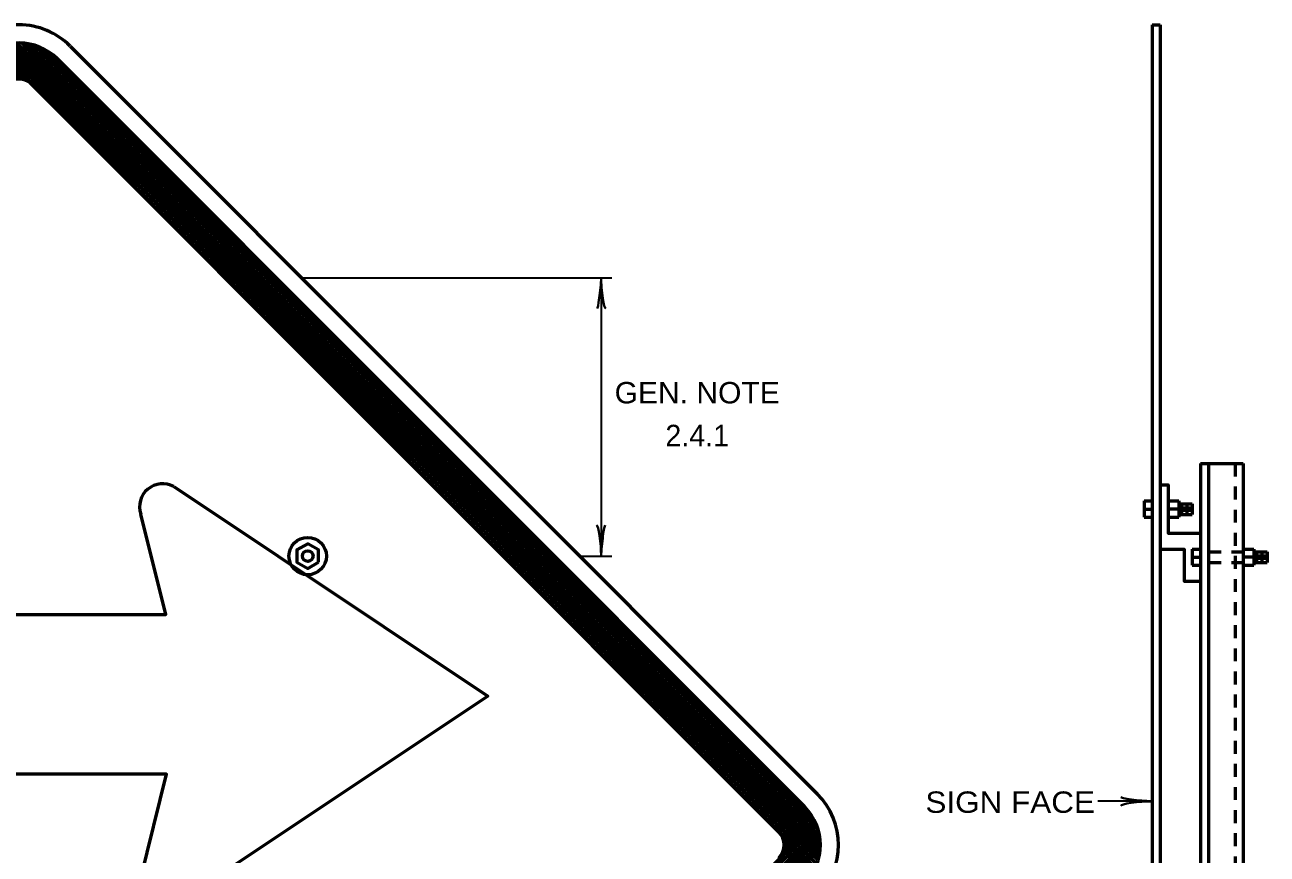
# Model space of a CAD drawing. Extents: x -87 to 768, y -466 to 78.
# Drawn here: x 318.2 to 457.7, y -128.5 to -35.5 of the extents above; entities that cross this region are included whole.
import ezdxf
from ezdxf.enums import TextEntityAlignment as Align

# ---------------------------------------------------------------- set-up
doc = ezdxf.new("R2010")
doc.units = 0
doc.header["$LTSCALE"] = 0.96
doc.linetypes.add('SHORT_DASHED', pattern=[2.7, 1.5, -1.2])
doc.layers.add('1', color=7, linetype='Continuous', lineweight=53)

msp = doc.modelspace()

# ---------------------------------------------------------------- linework, layer by layer
at = {"layer": '1'}
for p, q in [((444.7887, -35.5407), (444.7887, -219.495)), ((444.7887, -35.5407), (445.6887, -35.5407)), ((445.6887, -35.5407), (445.6887, -219.495)), ((407.486, -128.2899), (316.8201, -37.6241)), ((407.5279, -127.7575), (317.3498, -37.5794)), ((407.5218, -127.177), (317.9254, -37.5806)), ((227.7254, -128.5202), (318.5878, -37.658)), ((227.8255, -128.9946), (319.0635, -37.7564)), ((227.9554, -129.4392), (319.5087, -37.8858)), ((228.1115, -129.8572), (319.9271, -38.0419)), ((406.9712, -130.0724), (315.0351, -38.1363)), ((407.1407, -129.6676), (315.4397, -37.9668)), ((407.2851, -129.2377), (315.8698, -37.8226)), ((407.4015, -128.7799), (316.3286, -37.7069)), ((316.705, -41.8382), (320.3206, -38.2224)), ((317.4781, -41.6393), (320.6918, -38.4255)), ((318.0107, -41.681), (321.0421, -38.6497)), ((318.4425, -41.8238), (321.3724, -38.8939)), ((407.4553, -126.536), (318.5748, -37.6557)), ((407.2808, -125.7873), (319.318, -37.8244)), ((406.9208, -124.8529), (320.2609, -38.1932)), ((323.3322, -37.9197), (407.1871, -121.7745)), ((318.8028, -42.0377), (321.6832, -39.1574)), ((319.1061, -42.3088), (321.9778, -39.437)), ((319.3933, -42.596), (322.265, -39.7242)), ((319.6804, -42.8831), (322.5523, -40.0115)), ((319.9675, -43.1704), (322.8394, -40.2985)), ((405.7511, -123.2103), (321.8964, -39.3556)), ((320.2547, -43.4576), (323.1265, -40.5857)), ((320.542, -43.7445), (323.4136, -40.8729)), ((320.8291, -44.0318), (323.7009, -41.16)), ((321.1163, -44.319), (323.988, -41.4473)), ((321.4035, -44.6061), (324.2752, -41.7343)), ((402.8792, -126.0818), (319.0244, -42.2273)), ((321.6907, -44.8934), (324.5625, -42.0216)), ((321.9778, -45.1806), (324.8496, -42.3088)), ((322.265, -45.4677), (325.1367, -42.5959)), ((322.5522, -45.7549), (325.424, -42.8831)), ((322.8394, -46.0421), (325.7112, -43.1704)), ((323.1265, -46.3292), (325.9983, -43.4574)), ((323.4136, -46.6165), (326.2856, -43.7445)), ((323.7009, -46.9036), (326.5725, -44.0318)), ((323.988, -47.1907), (326.8598, -44.3189)), ((324.2752, -47.478), (327.147, -44.6061)), ((324.5624, -47.765), (327.4341, -44.8934)), ((324.8496, -48.0523), (327.7213, -45.1805)), ((325.1367, -48.3395), (328.0086, -45.4677)), ((325.4239, -48.6266), (328.2957, -45.7549)), ((325.7112, -48.9138), (328.5828, -46.042)), ((325.9983, -49.201), (328.8702, -46.3292)), ((326.2854, -49.4881), (329.1572, -46.6165)), ((326.5725, -49.7754), (329.4444, -46.9034)), ((326.8598, -50.0626), (329.7316, -47.1907)), ((327.1469, -50.3495), (330.0187, -47.478)), ((327.4341, -50.6369), (330.3058, -47.765)), ((327.7213, -50.924), (330.593, -48.0523)), ((328.0085, -51.2111), (330.8803, -48.3395)), ((328.2957, -51.4984), (331.1674, -48.6266)), ((328.5828, -51.7856), (331.4546, -48.9137)), ((328.8701, -52.0726), (331.7417, -49.201)), ((329.1572, -52.3599), (332.029, -49.4881)), ((329.4444, -52.6472), (332.3161, -49.7752)), ((329.7314, -52.9342), (332.6033, -50.0626)), ((330.0187, -53.2215), (332.8905, -50.3495)), ((330.3058, -53.5086), (333.1776, -50.6368)), ((330.593, -53.7957), (333.4648, -50.924)), ((330.8803, -54.0829), (333.752, -51.2111)), ((331.1674, -54.3701), (334.0392, -51.4983)), ((331.4546, -54.6572), (334.3263, -51.7856)), ((331.7416, -54.9444), (334.6136, -52.0726)), ((332.029, -55.2317), (334.9006, -52.3598)), ((332.3161, -55.5188), (335.1879, -52.6472)), ((332.6031, -55.806), (335.4751, -52.9342)), ((332.8905, -56.0932), (335.7622, -53.2213)), ((333.1776, -56.3804), (336.0494, -53.5086)), ((333.4647, -56.6673), (336.3367, -53.7957)), ((333.752, -56.9548), (336.6237, -54.0828)), ((334.0392, -57.2419), (336.9108, -54.3701)), ((334.3262, -57.5289), (337.1981, -54.6572)), ((334.6136, -57.8162), (337.4852, -54.9444)), ((334.9006, -58.1034), (337.7723, -55.2317)), ((335.1878, -58.3905), (338.0597, -55.5188)), ((335.4751, -58.6777), (338.3468, -55.806)), ((335.7622, -58.965), (338.6339, -56.0929)), ((336.0492, -59.252), (338.9212, -56.3804)), ((336.3367, -59.5393), (339.2083, -56.6673)), ((336.6237, -59.8265), (339.4953, -56.9545)), ((336.9107, -60.1135), (339.7828, -57.2419)), ((337.1981, -60.4009), (340.0697, -57.5289)), ((337.4852, -60.6879), (340.3569, -57.8161)), ((337.7723, -60.9751), (340.6443, -58.1034)), ((338.0597, -61.2623), (340.9313, -58.3905)), ((338.3468, -61.5495), (341.2185, -58.6775)), ((338.6339, -61.8365), (341.5058, -58.965)), ((338.9209, -62.1237), (341.7929, -59.252)), ((339.2083, -62.4111), (342.08, -59.539)), ((339.4953, -62.6981), (342.3673, -59.8265)), ((339.7825, -62.9852), (342.6544, -60.1135)), ((340.0697, -63.2726), (342.9415, -60.4006)), ((340.3569, -63.5596), (343.2289, -60.6879)), ((340.6441, -63.8467), (343.5158, -60.9751)), ((340.9313, -64.134), (343.8031, -61.2621)), ((341.2185, -64.4211), (344.0903, -61.5495)), ((341.5056, -64.7083), (344.3774, -61.8365)), ((341.7929, -64.9956), (344.6646, -62.1237)), ((342.08, -65.2827), (344.9517, -62.4111)), ((342.367, -65.5699), (345.2389, -62.6981)), ((342.6544, -65.8571), (345.5261, -62.9852)), ((342.9415, -66.1442), (345.8132, -63.2726)), ((343.2286, -66.4313), (346.1005, -63.5596)), ((343.5158, -66.7187), (346.3876, -63.8467)), ((343.8031, -67.0057), (346.6747, -64.134)), ((344.0901, -67.2929), (346.962, -64.4211)), ((344.3774, -67.5802), (347.2491, -64.7083)), ((344.6646, -67.8672), (347.5362, -64.9955)), ((344.9517, -68.1544), (347.8235, -65.2827)), ((345.2389, -68.4417), (348.1107, -65.5699)), ((345.5261, -68.7288), (348.3978, -65.857)), ((345.8132, -69.0159), (348.685, -66.1442)), ((346.1005, -69.3032), (348.9723, -66.4313)), ((346.3876, -69.5903), (349.2592, -66.7185)), ((346.6747, -69.8774), (349.5466, -67.0057)), ((346.9619, -70.1646), (349.8336, -67.2929)), ((347.2491, -70.4517), (350.1208, -67.5801)), ((347.5362, -70.739), (350.4081, -67.8672)), ((347.8235, -71.0261), (350.6952, -68.1544)), ((348.1107, -71.3133), (350.9824, -68.4416)), ((348.3978, -71.6005), (351.2697, -68.7288)), ((348.6849, -71.8877), (351.5568, -69.0159)), ((348.9723, -72.1749), (351.8438, -69.3031)), ((349.2592, -72.462), (352.1312, -69.5903)), ((349.5465, -72.7493), (352.4183, -69.8774)), ((349.8336, -73.0364), (352.7053, -70.1646)), ((350.1208, -73.3235), (352.9926, -70.4517)), ((350.4081, -73.6106), (353.2798, -70.739)), ((350.6952, -73.898), (353.5669, -71.0261)), ((350.9824, -74.185), (353.8541, -71.3132)), ((351.2696, -74.4722), (354.1414, -71.6005)), ((351.5568, -74.7596), (354.4284, -71.8877)), ((351.8438, -75.0466), (354.7157, -72.1748)), ((352.1312, -75.3338), (355.0028, -72.462)), ((352.4183, -75.621), (355.29, -72.7493)), ((352.7053, -75.9082), (355.5773, -73.0363)), ((352.9926, -76.1953), (355.8644, -73.3235)), ((353.2798, -76.4826), (356.1514, -73.6106)), ((353.5669, -76.7696), (356.4387, -73.8979)), ((353.8541, -77.0568), (356.7259, -74.185)), ((354.1413, -77.344), (357.0129, -74.4722)), ((354.4284, -77.6311), (357.3003, -74.7595)), ((354.7157, -77.9184), (357.5874, -75.0466)), ((355.0028, -78.2055), (357.8745, -75.3338)), ((355.29, -78.4927), (358.1618, -75.6209)), ((355.5773, -78.7798), (358.449, -75.9082)), ((355.8642, -79.0671), (358.7361, -76.1953)), ((356.1514, -79.3542), (359.0233, -76.4824)), ((356.4387, -79.6414), (359.3103, -76.7696)), ((356.7258, -79.9285), (359.5976, -77.0568)), ((357.0129, -80.2157), (359.8848, -77.344)), ((357.3003, -80.5029), (360.1719, -77.6311)), ((357.5874, -80.79), (360.4592, -77.9184)), ((357.8745, -81.0773), (360.7464, -78.2055)), ((358.1618, -81.3644), (361.0334, -78.4927)), ((358.4489, -81.6516), (361.3207, -78.7798)), ((358.7361, -81.9388), (361.6079, -79.0671)), ((359.0233, -82.226), (361.895, -79.3541)), ((359.3103, -82.5132), (362.1822, -79.6414)), ((359.5976, -82.8003), (362.4694, -79.9285)), ((359.8848, -83.0876), (362.7565, -80.2156)), ((360.1719, -83.3746), (363.0437, -80.5029)), ((360.4592, -83.6618), (363.3309, -80.79)), ((360.7464, -83.949), (363.618, -81.0772)), ((361.0334, -84.2362), (363.9053, -81.3644)), ((361.3206, -84.5233), (364.1924, -81.6516)), ((361.6079, -84.8106), (364.4795, -81.9387)), ((361.895, -85.0977), (364.7668, -82.226)), ((362.1821, -85.3848), (365.054, -82.5132)), ((362.4694, -85.6722), (365.3411, -82.8001)), ((362.7565, -85.9592), (365.6283, -83.0876)), ((363.0436, -86.2462), (365.9156, -83.3746)), ((363.3309, -86.5337), (366.2025, -83.6617)), ((363.618, -86.8207), (366.4897, -83.949)), ((363.9052, -87.1078), (366.7769, -84.2362)), ((364.1924, -87.3951), (367.0641, -84.5233)), ((364.4795, -87.6823), (367.3513, -84.8106)), ((450.1887, -84.7407), (450.1887, -317.295)), ((450.1887, -84.7407), (454.9887, -84.7407)), ((451.0887, -84.7407), (451.0887, -317.295)), ((454.9887, -84.7407), (454.9887, -317.295)), ((364.7667, -87.9693), (367.6385, -85.0977)), ((365.054, -88.2567), (367.9257, -85.3848)), ((365.3411, -88.5438), (368.2128, -85.6722)), ((365.6281, -88.8309), (368.5001, -85.9592)), ((365.9156, -89.1182), (368.7872, -86.2462)), ((366.2025, -89.4053), (369.0743, -86.5335)), ((366.4897, -89.6924), (369.3616, -86.8207)), ((366.7769, -89.9798), (369.6487, -87.1078)), ((367.0641, -90.2668), (369.9359, -87.395)), ((367.3513, -90.554), (370.2231, -87.6823)), ((367.6385, -90.8413), (370.5103, -87.9693)), ((367.9257, -91.1283), (370.7973, -88.2565)), ((368.2128, -91.4155), (371.0847, -88.5438)), ((368.4998, -91.7027), (371.3718, -88.8309)), ((368.7872, -91.9899), (371.6589, -89.118)), ((443.8887, -88.9407), (444.7887, -88.9407)), ((443.8887, -88.9407), (443.8887, -90.7407)), ((446.5887, -88.9407), (447.7887, -88.9407)), ((447.7887, -88.9407), (447.7887, -90.7407)), ((447.7887, -89.2407), (449.2887, -89.2407)), ((448.0887, -89.2407), (448.0887, -90.4407)), ((448.6887, -89.2407), (448.6887, -90.4407)), ((449.2887, -89.2407), (449.2887, -90.4407)), ((369.0743, -92.2771), (371.9461, -89.4053)), ((369.3613, -92.564), (372.2334, -89.6924)), ((369.6487, -92.8515), (372.5204, -89.9795)), ((369.9359, -93.1385), (372.8077, -90.2668)), ((370.2229, -93.4256), (373.0948, -90.554)), ((443.8887, -89.8407), (444.7887, -89.8407)), ((447.7887, -89.8407), (446.5887, -89.8407)), ((447.7887, -90.4407), (449.2887, -90.4407)), ((448.3887, -89.5407), (448.3887, -90.1407)), ((448.9887, -89.5407), (448.9887, -90.1407)), ((370.5103, -93.7128), (373.3819, -90.8411)), ((370.7973, -94.0001), (373.669, -91.1283)), ((371.0845, -94.2872), (373.9563, -91.4155)), ((371.3718, -94.5744), (374.2435, -91.7027)), ((371.6589, -94.8617), (374.5305, -91.9899)), ((443.8887, -90.7407), (444.7887, -90.7407)), ((446.5887, -90.7407), (447.7887, -90.7407)), ((371.9459, -95.1487), (374.8179, -92.2771)), ((372.2334, -95.436), (375.105, -92.564)), ((372.5204, -95.7231), (375.3921, -92.8515)), ((372.8074, -96.0102), (375.6795, -93.1385)), ((373.0948, -96.2975), (375.9664, -93.4256)), ((373.3819, -96.5846), (376.2537, -93.7128)), ((373.669, -96.8718), (376.5409, -94.0001)), ((373.9563, -97.159), (376.828, -94.2872)), ((374.2435, -97.4462), (377.1152, -94.5743)), ((449.2887, -94.3407), (450.1887, -94.3407)), ((449.2887, -94.3407), (449.2887, -96.1407)), ((454.9887, -94.3407), (456.1887, -94.3407)), ((456.1887, -94.3407), (456.1887, -96.1407)), ((456.1887, -94.6407), (457.6887, -94.6407)), ((456.4887, -94.6407), (456.4887, -95.8407)), ((457.0887, -94.6407), (457.0887, -95.8407)), ((457.6887, -94.6407), (457.6887, -95.8407)), ((374.5305, -97.7332), (377.4025, -94.8617)), ((374.8179, -98.0206), (377.6896, -95.1487)), ((375.105, -98.3077), (377.9767, -95.4359)), ((375.3921, -98.5948), (378.264, -95.7231)), ((375.6795, -98.882), (378.5511, -96.0102)), ((449.2887, -95.2407), (450.1887, -95.2407)), ((449.2887, -96.1407), (450.1887, -96.1407)), ((456.1887, -95.2407), (454.9887, -95.2407)), ((454.9887, -96.1407), (456.1887, -96.1407)), ((456.1887, -95.8407), (457.6887, -95.8407)), ((456.7887, -94.9407), (456.7887, -95.5407)), ((457.3887, -94.9407), (457.3887, -95.5407)), ((375.9664, -99.1693), (378.8382, -96.2973)), ((376.2537, -99.4563), (379.1255, -96.5846)), ((376.5408, -99.7435), (379.4125, -96.8718)), ((376.828, -100.0307), (379.6998, -97.1589)), ((377.1152, -100.3178), (379.987, -97.4462)), ((377.4024, -100.6051), (380.2741, -97.7332)), ((377.6896, -100.8922), (380.5613, -98.0205)), ((377.9767, -101.1794), (380.8485, -98.3077)), ((378.2639, -101.4666), (381.1356, -98.5948)), ((378.5511, -101.7538), (381.4228, -98.882)), ((378.8382, -102.0409), (381.71, -99.1693)), ((379.1253, -102.3282), (381.9972, -99.4563)), ((379.4125, -102.6154), (382.2843, -99.7435)), ((379.6998, -102.9023), (382.5714, -100.0307)), ((379.9869, -103.1896), (382.8587, -100.3178)), ((380.2741, -103.4768), (383.1458, -100.6051)), ((380.5613, -103.7639), (383.433, -100.8922)), ((380.8485, -104.0512), (383.7202, -101.1794)), ((381.1356, -104.3384), (384.0074, -101.4666)), ((381.4228, -104.6255), (384.2945, -101.7537)), ((381.71, -104.9127), (384.5817, -102.0409)), ((381.9972, -105.1999), (384.869, -102.3282)), ((382.2843, -105.487), (385.1561, -102.6152)), ((382.5714, -105.7743), (385.4433, -102.9023)), ((382.8587, -106.0614), (385.7303, -103.1896)), ((383.1458, -106.3484), (386.0176, -103.4767)), ((383.433, -106.6358), (386.3048, -103.7639)), ((383.7201, -106.9228), (386.5919, -104.0512)), ((384.0074, -107.21), (386.8791, -104.3383)), ((384.2945, -107.4973), (387.1664, -104.6255)), ((384.5817, -107.7844), (387.4535, -104.9127)), ((384.869, -108.0716), (387.7406, -105.1998)), ((385.1561, -108.3588), (388.0279, -105.487)), ((385.4432, -108.6459), (388.315, -105.7743)), ((385.7303, -108.9332), (388.6022, -106.0612)), ((386.0176, -109.2204), (388.8892, -106.3484)), ((386.3047, -109.5073), (389.1765, -106.6358)), ((386.5919, -109.7947), (389.4636, -106.9228)), ((386.8791, -110.0818), (389.7508, -107.21)), ((387.1663, -110.3689), (390.0381, -107.4973)), ((387.4535, -110.6562), (390.3252, -107.7844)), ((387.7406, -110.9434), (390.6124, -108.0716)), ((388.0279, -111.2304), (390.8995, -108.3588)), ((388.315, -111.5177), (391.1868, -108.6459)), ((388.6022, -111.805), (391.4739, -108.9332)), ((388.8892, -112.092), (391.7611, -109.2204)), ((389.1765, -112.3793), (392.0482, -109.5073)), ((389.4636, -112.6664), (392.3354, -109.7946)), ((389.7508, -112.9535), (392.6226, -110.0818)), ((390.0381, -113.2407), (392.9097, -110.3689)), ((390.3252, -113.5279), (393.197, -110.6561)), ((390.6124, -113.815), (393.4841, -110.9434)), ((390.8994, -114.1022), (393.7713, -111.2304)), ((391.1868, -114.3895), (394.0584, -111.5176)), ((391.4739, -114.6765), (394.3457, -111.805)), ((391.7609, -114.9638), (394.6329, -112.092)), ((392.0482, -115.251), (394.92, -112.3791)), ((392.3354, -115.5381), (395.207, -112.6664)), ((392.6225, -115.8251), (395.4945, -112.9535)), ((392.9097, -116.1126), (395.7815, -113.2406)), ((393.197, -116.3996), (396.0685, -113.5279)), ((393.484, -116.6867), (396.3559, -113.815)), ((393.7713, -116.974), (396.643, -114.1022)), ((394.0584, -117.2612), (396.9301, -114.3895)), ((394.3456, -117.5483), (397.2175, -114.6765)), ((394.6329, -117.8355), (397.5046, -114.9638)), ((394.92, -118.1228), (397.7917, -115.251)), ((395.207, -118.4098), (398.079, -115.5381)), ((395.4945, -118.6971), (398.3661, -115.8251)), ((395.7815, -118.9843), (398.6531, -116.1126)), ((396.0685, -119.2713), (398.9406, -116.3996)), ((396.3559, -119.5587), (399.2275, -116.6867)), ((396.643, -119.8457), (399.5147, -116.9739)), ((396.9301, -120.1329), (399.8021, -117.2612)), ((397.2175, -120.4201), (400.0891, -117.5483)), ((397.5046, -120.7073), (400.3762, -117.8353)), ((397.7917, -120.9943), (400.6636, -118.1228)), ((398.0787, -121.2815), (400.9507, -118.4098)), ((398.3661, -121.5689), (401.2377, -118.6968)), ((398.6531, -121.8559), (401.5251, -118.9843)), ((398.9403, -122.1429), (401.8122, -119.2713)), ((399.2275, -122.4304), (402.0993, -119.5584)), ((399.5147, -122.7174), (402.3864, -119.8457)), ((399.8019, -123.0044), (402.6736, -120.1329)), ((400.0891, -123.2918), (402.9609, -120.4199)), ((400.3762, -123.5789), (403.2479, -120.7073)), ((400.6634, -123.866), (403.5352, -120.9943)), ((400.9507, -124.1534), (403.8224, -121.2815)), ((401.2377, -124.4405), (404.1095, -121.5689)), ((401.5248, -124.7276), (404.3967, -121.8559)), ((401.8122, -125.0149), (404.6839, -122.1429)), ((402.0993, -125.302), (404.971, -122.4304)), ((402.3864, -125.5891), (405.2583, -122.7174)), ((402.6736, -125.8765), (405.5454, -123.0044)), ((402.9581, -126.1663), (405.8311, -123.2934)), ((403.1972, -126.5015), (406.1014, -123.5973)), ((403.3737, -126.8994), (406.3539, -123.919)), ((315.0754, -216.9205), (406.9894, -125.0068)), ((315.4829, -217.0877), (407.1564, -125.414)), ((403.4097, -128.0119), (406.7989, -124.6228)), ((403.4664, -127.3812), (406.5867, -124.2607)), ((315.9156, -217.2292), (407.2976, -125.8472)), ((316.3767, -217.3424), (407.4101, -126.3091)), ((316.8732, -217.4203), (407.4895, -126.8039)), ((317.4098, -217.4581), (407.5305, -127.3374)), ((317.9951, -217.4472), (407.5197, -127.9224)), ((406.3305, -131.1548), (403.3581, -128.1824)), ((406.7787, -130.4543), (403.4291, -127.105)), ((406.5646, -130.8147), (403.4607, -127.7108))]:
    msp.add_line(p, q, dxfattribs=at)
at = {"layer": '1', "lineweight": 35}
for p, q in [((349.3303, -63.9178), (384.1304, -63.9178)), ((382.9304, -63.9178), (382.9304, -95.1178)), ((380.5304, -95.1178), (384.1304, -95.1178)), ((444.6993, -122.6195), (438.6993, -122.6195))]:
    msp.add_line(p, q, dxfattribs=at)
at = {"layer": '1', "linetype": 'SHORT_DASHED'}
for p, q in [((454.0887, -84.7407), (454.0887, -317.295)), ((451.0887, -94.6407), (454.9887, -94.6407)), ((451.0887, -95.8407), (454.9887, -95.8407))]:
    msp.add_line(p, q, dxfattribs=at)
at = {"layer": '1'}
for points in [[(334.9582, -87.3242), (370.209, -110.8248), (334.9582, -134.3253)], [(445.6887, -87.1407), (446.5887, -87.1407), (446.5887, -92.5407), (450.1887, -92.5407)], [(302.0737, -101.6613), (334.0586, -101.6613), (331.2476, -90.4165)], [(445.6887, -94.3407), (448.3887, -94.3407), (448.3887, -97.9407), (450.1887, -97.9407)], [(331.2476, -131.2331), (334.1568, -119.596), (308.828, -119.596)]]:
    msp.add_lwpolyline(points, dxfattribs=at)
msp.add_lwpolyline([(351.1887, -95.8106), (351.1887, -94.425), (349.9887, -93.7322), (348.7887, -94.425), (348.7887, -95.8106), (349.9887, -96.5034)], close=True, dxfattribs=at)
for radius in [2.1, 0.6]:
    msp.add_circle((349.9887, -95.1178), radius, dxfattribs=at)
for centre, radius, start, end in [((317.5888, -43.6632), 8.1225, 45, 135.00032), ((317.5888, -43.6632), 6.0919, 45, 135.00032), ((317.5888, -43.6632), 2.0306, 45, 135.00032), ((333.7063, -89.5944), 2.5925, 61.12617, 198.48578), ((401.4434, -127.5178), 8.1225, 315, 45), ((401.4434, -127.5178), 6.0919, 315, 45), ((401.4434, -127.5178), 2.0306, 315, 45)]:
    msp.add_arc(centre, radius, start, end, dxfattribs=at)
at = {"layer": '1', "lineweight": 40}
for centre, major_axis, ratio, start_param, end_param in [((382.6765, -65.2624), (0.2108, 2.1077), 0.07063, 3.14071475, 5.41810995), ((382.6765, -65.2624), (0.2108, 2.1077), 0.07063, 3.14071475, 5.41810995), ((383.262, -65.2272), (-0.1874, 2.1428), 0.122415, 0.89635335, 3.14159265), ((383.262, -65.2272), (-0.1874, 2.1428), 0.122415, 0.89635335, 3.14159265), ((382.5988, -93.8084), (0.1874, -2.1428), 0.122415, 0.89635335, 3.14159265), ((383.1843, -93.7732), (-0.2108, -2.1077), 0.07063, 3.14071475, 5.41810995), ((443.3899, -122.9511), (2.1428, 0.1874), 0.122415, 0.89635335, 3.14159265), ((443.3547, -122.3656), (2.1077, -0.2108), 0.07063, 3.14071475, 5.41810995)]:
    msp.add_ellipse(centre, major_axis=major_axis, ratio=ratio, start_param=start_param, end_param=end_param, dxfattribs=at)

# ---------------------------------------------------------------- texts
at = {"layer": '1'}
for s, width, p in [('GEN. NOTE', 1.05, (393.7116, -77.9941)), ('SIGN FACE', 1.1, (428.8434, -123.9167))]:
    msp.add_text(s, height=2.4, dxfattribs=dict(at, width=width)).set_placement(p, align=Align.CENTER)
msp.add_text('2.4.1', height=2.4, dxfattribs=at).set_placement((393.7116, -82.7941), align=Align.CENTER)

doc.saveas('drawing.dxf')
